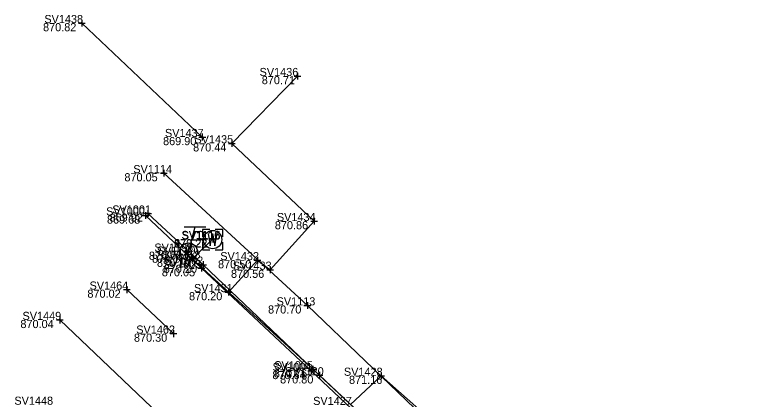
# Model space of a CAD drawing. Extents: x 1480001 to 1480402, y 379235 to 379603.
# Drawn here: x 1480023.7 to 1480133.3, y 379546.7 to 379603.4 of the extents above; entities that cross this region are included whole.
import ezdxf

# ---------------------------------------------------------------- set-up
doc = ezdxf.new("R2010")
doc.units = 0
for name, color, linetype in [('BD_X_Building', 7, 'Continuous'), ('PM_P_CL_Double_Solid', 7, 'Continuous'), ('PM_X_Lane_Line', 7, 'Continuous'), ('PV_X_Curb', 7, 'Continuous'), ('PV_X_Driveway', 7, 'Continuous'), ('PV_X_Walk', 7, 'Continuous'), ('SV_X_Shot_Marker', 7, 'Continuous'), ('SV_X_Text_Elevation', 7, 'Continuous'), ('SV_X_Text_Name', 7, 'Continuous'), ('UT_X_Misc_Cells', 7, 'Continuous'), ('UT_X_Water', 7, 'Continuous'), ('UT_X_Water_Cells', 7, 'Continuous')]:
    doc.layers.add(name, color=color, linetype=linetype)

msp = doc.modelspace()

# ---------------------------------------------------------------- linework, layer by layer
at = {"layer": 'BD_X_Building'}
msp.add_line((1480051.32, 379585.39), (1480033.54, 379602.22), dxfattribs=at)
at = {"layer": 'PM_P_CL_Double_Solid'}
msp.add_lwpolyline([(1480030.31, 379558.37), (1480048.99, 379540.54), (1480068.18, 379522.46), (1480086.7, 379505.16), (1480104.25, 379488.61), (1480122.28, 379471.9), (1480139.96, 379455.6)], dxfattribs=at)
at = {"layer": 'PM_X_Lane_Line'}
msp.add_line((1480047.08, 379556.35), (1480040.19, 379562.85), dxfattribs=at)
at = {"layer": 'PV_X_Curb'}
for points in [[(1480043.31, 379574.09), (1480051.44, 379566.53), (1480067.64, 379551.08), (1480087.83, 379532.14), (1480105.19, 379515.82), (1480105.94, 379515.2), (1480115.29, 379506.59), (1480116.59, 379505.38), (1480117, 379505.56), (1480121.37, 379501.34), (1480121.05, 379501.14), (1480146.64, 379476.91), (1480171.18, 379454.1), (1480173.02, 379452.23), (1480182.18, 379443.68), (1480183.38, 379442.68), (1480186.18, 379440.01), (1480186.98, 379439.36), (1480207.41, 379420.3)], [(1480042.95, 379573.8), (1480051.18, 379566.02), (1480067.38, 379550.83), (1480087.59, 379531.81), (1480105.07, 379515.41), (1480105.59, 379514.89), (1480115.08, 379506.3), (1480116.3, 379505.05), (1480118.53, 379502.97), (1480120.9, 379500.82), (1480138.71, 379483.7), (1480170.84, 379453.68), (1480172.57, 379452.08), (1480181.87, 379443.35), (1480182.84, 379442.22), (1480185.61, 379439.66), (1480186.49, 379438.95), (1480206.92, 379419.86)]]:
    msp.add_lwpolyline(points, dxfattribs=at)
at = {"layer": 'PV_X_Driveway'}
for points in [[(1480055.16, 379562.48), (1480059.47, 379567.2), (1480061.34, 379565.79), (1480067.81, 379572.97), (1480055.67, 379584.46), (1480065.36, 379594.4)], [(1480073.14, 379545.81), (1480077.69, 379550.12), (1480090.06, 379539.2), (1480093.89, 379543.58)]]:
    msp.add_lwpolyline(points, dxfattribs=at)
at = {"layer": 'PV_X_Walk'}
msp.add_lwpolyline([(1480235.61, 379401.34), (1480215.34, 379421.05), (1480197.47, 379437.46), (1480177.8, 379455.97), (1480154.79, 379476.97), (1480132.75, 379497.48), (1480113.38, 379516.73), (1480110.75, 379519.04), (1480109.88, 379518.34), (1480091.94, 379535.27), (1480093.03, 379536.62), (1480090.22, 379539.24), (1480090.46, 379539.73), (1480084.68, 379544.88), (1480083.84, 379544.14), (1480066.82, 379560.52), (1480045.66, 379580.05)], dxfattribs=at)
at = {"layer": 'SV_X_Shot_Marker'}
for p, q in [((1480033.54, 379602.72), (1480033.54, 379601.72)), ((1480033.04, 379602.22), (1480034.04, 379602.22)), ((1480033.54, 379602.22), (1480033.54, 379602.22)), ((1480065.36, 379594.9), (1480065.36, 379593.9)), ((1480064.86, 379594.4), (1480065.86, 379594.4)), ((1480065.36, 379594.4), (1480065.36, 379594.4)), ((1480050.82, 379585.39), (1480051.82, 379585.39)), ((1480051.32, 379585.89), (1480051.32, 379584.89)), ((1480051.32, 379585.39), (1480051.32, 379585.39)), ((1480055.67, 379584.96), (1480055.67, 379583.96)), ((1480055.17, 379584.46), (1480056.17, 379584.46)), ((1480055.67, 379584.46), (1480055.67, 379584.46)), ((1480045.66, 379580.55), (1480045.66, 379579.55)), ((1480045.16, 379580.05), (1480046.16, 379580.05)), ((1480045.66, 379580.05), (1480045.66, 379580.05)), ((1480042.81, 379574.09), (1480043.81, 379574.09)), ((1480042.95, 379574.3), (1480042.95, 379573.3)), ((1480043.31, 379574.59), (1480043.31, 379573.59)), ((1480043.31, 379574.09), (1480043.31, 379574.09)), ((1480042.45, 379573.8), (1480043.45, 379573.8)), ((1480042.95, 379573.8), (1480042.95, 379573.8)), ((1480067.31, 379572.97), (1480068.31, 379572.97)), ((1480067.81, 379573.47), (1480067.81, 379572.47)), ((1480067.81, 379572.97), (1480067.81, 379572.97)), ((1480052.86, 379570.83), (1480052.86, 379569.83)), ((1480052.36, 379570.33), (1480053.36, 379570.33)), ((1480052.86, 379570.33), (1480052.86, 379570.33)), ((1480049.15, 379568.52), (1480049.15, 379567.52)), ((1480048.65, 379568.02), (1480049.65, 379568.02)), ((1480049.15, 379568.02), (1480049.15, 379568.02)), ((1480049.39, 379567.42), (1480050.39, 379567.42)), ((1480049.89, 379567.92), (1480049.89, 379566.92)), ((1480049.89, 379567.42), (1480049.89, 379567.42)), ((1480059.47, 379567.7), (1480059.47, 379566.7)), ((1480050.94, 379566.53), (1480051.94, 379566.53)), ((1480051.18, 379566.52), (1480051.18, 379565.52)), ((1480051.44, 379567.03), (1480051.44, 379566.03)), ((1480051.44, 379566.53), (1480051.44, 379566.53)), ((1480058.97, 379567.2), (1480059.97, 379567.2)), ((1480059.47, 379567.2), (1480059.47, 379567.2)), ((1480061.34, 379566.29), (1480061.34, 379565.29)), ((1480050.68, 379566.02), (1480051.68, 379566.02)), ((1480051.18, 379566.02), (1480051.18, 379566.02)), ((1480060.84, 379565.79), (1480061.84, 379565.79)), ((1480061.34, 379565.79), (1480061.34, 379565.79)), ((1480040.19, 379563.35), (1480040.19, 379562.35)), ((1480055.16, 379562.98), (1480055.16, 379561.98)), ((1480039.69, 379562.85), (1480040.69, 379562.85)), ((1480040.19, 379562.85), (1480040.19, 379562.85)), ((1480054.66, 379562.48), (1480055.66, 379562.48)), ((1480055.16, 379562.48), (1480055.16, 379562.48)), ((1480066.82, 379561.02), (1480066.82, 379560.02)), ((1480066.32, 379560.52), (1480067.32, 379560.52)), ((1480066.82, 379560.52), (1480066.82, 379560.52)), ((1480030.31, 379558.87), (1480030.31, 379557.87)), ((1480029.81, 379558.37), (1480030.81, 379558.37)), ((1480030.31, 379558.37), (1480030.31, 379558.37)), ((1480047.08, 379556.85), (1480047.08, 379555.85)), ((1480046.58, 379556.35), (1480047.58, 379556.35)), ((1480047.08, 379556.35), (1480047.08, 379556.35)), ((1480067.14, 379551.08), (1480068.14, 379551.08)), ((1480067.38, 379551.33), (1480067.38, 379550.33)), ((1480067.64, 379551.58), (1480067.64, 379550.58)), ((1480067.64, 379551.08), (1480067.64, 379551.08)), ((1480066.88, 379550.83), (1480067.88, 379550.83)), ((1480067.38, 379550.83), (1480067.38, 379550.83)), ((1480068.11, 379550.19), (1480069.11, 379550.19)), ((1480068.61, 379550.69), (1480068.61, 379549.69)), ((1480068.61, 379550.19), (1480068.61, 379550.19)), ((1480077.19, 379550.12), (1480078.19, 379550.12)), ((1480077.69, 379550.62), (1480077.69, 379549.62)), ((1480077.69, 379550.12), (1480077.69, 379550.12))]:
    msp.add_line(p, q, dxfattribs=at)
at = {"layer": 'UT_X_Misc_Cells'}
for p, q in [((1480051.84, 379572.06), (1480048.64, 379572.06)), ((1480050.24, 379572.06), (1480048.64, 379566.06)), ((1480050.08, 379571.46), (1480050.93, 379571.46)), ((1480049.74, 379570.19), (1480050.93, 379570.19))]:
    msp.add_line(p, q, dxfattribs=at)
msp.add_circle((1480049.28, 379568.46), 1.3, dxfattribs=at)
msp.add_arc((1480050.95, 379570.82), 0.638, 268.8767, 91.1233, dxfattribs=at)
at = {"layer": 'UT_X_Water'}
msp.add_line((1480052.86, 379570.33), (1480049.89, 379567.42), dxfattribs=at)
msp.add_lwpolyline([(1480049.15, 379568.02), (1480068.61, 379550.19), (1480086.4, 379533.42), (1480090.02, 379530.08), (1480102.3, 379519.13), (1480111.73, 379511.47), (1480120.33, 379509.14), (1480127.54, 379501.67), (1480127.91, 379496.4), (1480140.17, 379484.08), (1480149.09, 379474.71), (1480164.73, 379459.48), (1480172.62, 379452.5), (1480197.81, 379429.11), (1480212.63, 379415.68), (1480231.59, 379398.24)], dxfattribs=at)
at = {"layer": 'UT_X_Water_Cells'}
msp.add_line((1480052.84, 379570.24), (1480052.84, 379570.24), dxfattribs=at)
for points in [[(1480052.44, 379571.74), (1480051.34, 379571.74), (1480051.34, 379570.64)], [(1480054.34, 379570.64), (1480054.34, 379571.74), (1480053.24, 379571.74)], [(1480052.17, 379571.14), (1480052.5, 379569.34), (1480052.84, 379571.14), (1480053.17, 379569.34), (1480053.5, 379571.14)], [(1480051.34, 379569.84), (1480051.34, 379568.74), (1480052.44, 379568.74)], [(1480053.24, 379568.74), (1480054.34, 379568.74), (1480054.34, 379569.84)]]:
    msp.add_lwpolyline(points, dxfattribs=at)
msp.add_circle((1480052.84, 379570.24), 1.35, dxfattribs=at)

# ---------------------------------------------------------------- texts
at = {"layer": 'SV_X_Text_Elevation'}
for s, p in [('870.82', (1480027.83, 379601.02)), ('870.71', (1480060.09, 379593.2)), ('869.90', (1480045.53, 379584.19)), ('870.44', (1480049.96, 379583.26)), ('870.05', (1480039.83, 379578.85)), ('869.92', (1480037.64, 379572.89)), ('869.68', (1480037.26, 379572.6)), ('870.86', (1480062.02, 379571.77)), ('870.22', (1480047.15, 379569.04)), ('870.22', (1480047.17, 379569.13)), ('870.08', (1480043.44, 379567.26)), ('870.17', (1480043.91, 379566.82)), ('870.19', (1480044.63, 379566.22)), ('870.20', (1480045.63, 379565.33)), ('870.50', (1480053.64, 379566)), ('870.05', (1480045.35, 379564.82)), ('870.56', (1480055.55, 379564.59)), ('870.02', (1480034.37, 379561.65)), ('870.20', (1480049.36, 379561.28)), ('870.70', (1480061.02, 379559.32)), ('870.04', (1480024.49, 379557.17)), ('870.30', (1480041.24, 379555.15)), ('870.76', (1480061.87, 379549.88)), ('870.64', (1480061.66, 379549.63)), ('870.80', (1480062.79, 379548.99)), ('871.16', (1480072.96, 379548.92))]:
    msp.add_text(s, height=1.2, dxfattribs=at).set_placement(p)
at = {"layer": 'SV_X_Text_Name'}
for s, p in [('SV1438', (1480028.02, 379602.22)), ('SV1436', (1480059.77, 379594.4)), ('SV1437', (1480045.81, 379585.39)), ('SV1435', (1480050.16, 379584.46)), ('SV1114', (1480041.14, 379580.05)), ('SV1000', (1480037.14, 379573.8)), ('SV1001', (1480038.04, 379574.09)), ('SV1434', (1480062.32, 379572.97)), ('SV1116', (1480048.25, 379570.33)), ('SV1115', (1480048.3, 379570.24)), ('SV1198', (1480044.25, 379568.46)), ('SV1119', (1480044.61, 379568.02)), ('SV1118', (1480045.34, 379567.42)), ('SV1432', (1480053.97, 379567.2)), ('SV1002', (1480045.74, 379566.53)), ('SV1003', (1480045.48, 379566.02)), ('SV1433', (1480055.83, 379565.79)), ('SV1464', (1480034.69, 379562.85)), ('SV1431', (1480050.09, 379562.48)), ('SV1113', (1480062.28, 379560.52)), ('SV1449', (1480024.8, 379558.37)), ('SV1462', (1480041.58, 379556.35)), ('SV1004', (1480061.69, 379550.83)), ('SV1005', (1480061.93, 379551.08)), ('SV1120', (1480063.52, 379550.19)), ('SV1428', (1480072.21, 379550.12)), ('SV1448', (1480023.6, 379545.84)), ('SV1427', (1480067.67, 379545.81))]:
    msp.add_text(s, height=1.2, dxfattribs=at).set_placement(p)

doc.saveas('drawing.dxf')
